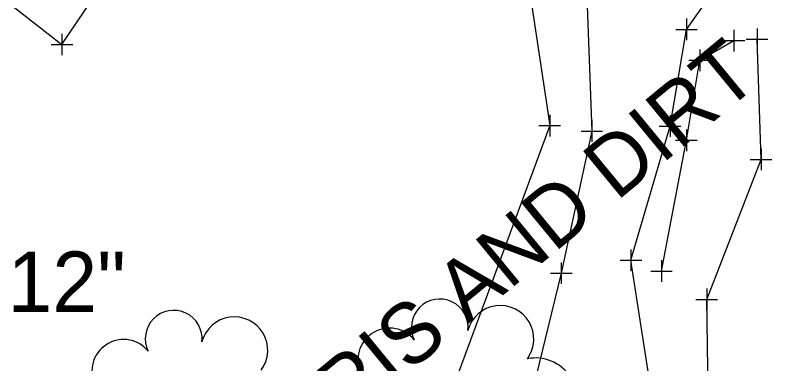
# Model space of a CAD drawing. Extents: x -4 to 139204, y -4 to 477121.
# Drawn here: x 139053.29 to 139088.39, y 477046.84 to 477063.01 of the extents above; entities that cross this region are included whole.
import ezdxf

# ---------------------------------------------------------------- set-up
doc = ezdxf.new("R2010")
doc.units = 0
for name, color, linetype in [('DR_X_Ditch', 7, 'Continuous'), ('GE_X_Alignment_100_Bearings', 7, 'Continuous'), ('GE_X_Alignment_100_Curve_Data', 7, 'Continuous'), ('SC_Scratch1', 7, 'Continuous'), ('SC_Scratch3', 7, 'Continuous'), ('SV_X_Text', 7, 'Continuous'), ('VG_X_Text', 7, 'Continuous')]:
    doc.layers.add(name, color=color, linetype=linetype)

msp = doc.modelspace()

# ---------------------------------------------------------------- linework, layer by layer
at = {"layer": 'DR_X_Ditch'}
for points in [[(139082.68, 477039.621), (139082.879, 477045.088), (139081.854, 477051.65), (139083.67, 477057.87), (139084.434, 477062.351), (139087.249, 477066.327), (139085.344, 477072.452), (139081.689, 477077.998), (139076.163, 477086.656), (139069.076, 477091.309)], [(139065.071, 477088.425), (139068.722, 477085.24), (139070.63, 477084.165), (139074.327, 477081.721), (139077.204, 477076.592), (139079.496, 477071.125), (139079.747, 477065.535), (139080.041, 477057.632), (139078.626, 477051.044), (139075.806, 477039.501), (139076.261, 477034.97)]]:
    msp.add_lwpolyline(points, dxfattribs=at)
at = {"layer": 'GE_X_Alignment_100_Bearings'}
for p, q in [((139084.434, 477062.851), (139084.434, 477061.851)), ((139083.934, 477062.351), (139084.934, 477062.351)), ((139084.434, 477062.351), (139084.434, 477062.351)), ((139086.636, 477062.331), (139086.636, 477061.331)), ((139087.707, 477062.392), (139087.707, 477061.392)), ((139055.462, 477062.152), (139055.462, 477061.152)), ((139054.962, 477061.652), (139055.962, 477061.652)), ((139055.462, 477061.652), (139055.462, 477061.652)), ((139086.136, 477061.831), (139087.136, 477061.831)), ((139086.636, 477061.831), (139086.636, 477061.831)), ((139087.207, 477061.892), (139088.207, 477061.892)), ((139087.707, 477061.892), (139087.707, 477061.892)), ((139085.047, 477061.419), (139085.047, 477060.419)), ((139084.547, 477060.919), (139085.547, 477060.919)), ((139085.047, 477060.919), (139085.047, 477060.919)), ((139078.09, 477058.388), (139078.09, 477057.388)), ((139080.041, 477058.132), (139080.041, 477057.132)), ((139083.67, 477058.37), (139083.67, 477057.37)), ((139077.59, 477057.888), (139078.59, 477057.888)), ((139078.09, 477057.888), (139078.09, 477057.888)), ((139083.17, 477057.87), (139084.17, 477057.87)), ((139083.67, 477057.87), (139083.67, 477057.87)), ((139079.541, 477057.632), (139080.541, 477057.632)), ((139080.041, 477057.632), (139080.041, 477057.632)), ((139084.426, 477057.707), (139084.426, 477056.707)), ((139083.926, 477057.207), (139084.926, 477057.207)), ((139084.426, 477057.207), (139084.426, 477057.207)), ((139087.893, 477056.82), (139087.893, 477055.82)), ((139087.393, 477056.32), (139088.393, 477056.32)), ((139087.893, 477056.32), (139087.893, 477056.32)), ((139081.854, 477052.15), (139081.854, 477051.15)), ((139078.626, 477051.544), (139078.626, 477050.544)), ((139081.354, 477051.65), (139082.354, 477051.65)), ((139081.854, 477051.65), (139081.854, 477051.65)), ((139083.272, 477051.641), (139083.272, 477050.641)), ((139082.772, 477051.141), (139083.772, 477051.141)), ((139083.272, 477051.141), (139083.272, 477051.141)), ((139078.126, 477051.044), (139079.126, 477051.044)), ((139078.626, 477051.044), (139078.626, 477051.044)), ((139085.371, 477050.327), (139085.371, 477049.327)), ((139084.871, 477049.827), (139085.871, 477049.827)), ((139085.371, 477049.827), (139085.371, 477049.827))]:
    msp.add_line(p, q, dxfattribs=at)
at = {"layer": 'GE_X_Alignment_100_Curve_Data'}
for centre, radius, start, end in [((139072.988, 477048.529), 1.317, 354.0047, 205.9741), ((139075.798, 477047.99), 1.553, 323.83, 165.0376), ((139060.648, 477048.003), 1.317, 354.0047, 205.9741), ((139063.458, 477047.464), 1.553, 323.83, 165.0376), ((139070.663, 477047.025), 1.471, 39.0625, 279.5412), ((139058.323, 477046.499), 1.471, 39.0625, 279.5412), ((139077.432, 477045.197), 1.915, 259.1453, 101.4596)]:
    msp.add_arc(centre, radius, start, end, dxfattribs=at)
at = {"layer": 'SC_Scratch1'}
msp.add_lwpolyline([(139085.531, 477039.177), (139085.371, 477049.827), (139087.893, 477056.32), (139087.707, 477061.892)], dxfattribs=at)
at = {"layer": 'SC_Scratch3'}
for points in [[(139053.686, 477090.637), (139058.184, 477084.596), (139059.86, 477080.901), (139058.705, 477075.881), (139051.633, 477067.64), (139051.641, 477064.627), (139055.462, 477061.652), (139060.738, 477069.452), (139063.498, 477071.098), (139065.609, 477066.813), (139071.131, 477068.017), (139073.573, 477072.991), (139076.409, 477069.09), (139078.09, 477057.888), (139073.469, 477045.379), (139071.206, 477039.094), (139066.85, 477033.126), (139068.313, 477027.937)], [(139083.272, 477051.141), (139084.426, 477057.207), (139085.047, 477060.919), (139086.636, 477061.831)]]:
    msp.add_lwpolyline(points, dxfattribs=at)

# ---------------------------------------------------------------- texts
at = {"layer": 'SV_X_Text'}
msp.add_text('PIPE COVERED BY DEBRIS AND DIRT', height=2.8, rotation=39.4837, dxfattribs=at).set_placement((139035.578, 477016.776))
at = {"layer": 'VG_X_Text'}
msp.add_text('12"', height=2.8, dxfattribs=at).set_placement((139052.935, 477049.249))

doc.saveas('drawing.dxf')
